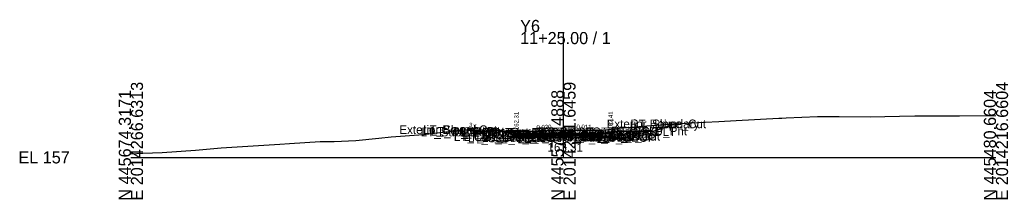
# Model space of a CAD drawing. Extents: x -26 to 203, y -10 to 4529.
# Drawn here: x -25.7 to 202.8, y 2490.3 to 2531.8 of the extents above; entities that cross this region are included whole.
import ezdxf

# ---------------------------------------------------------------- set-up
doc = ezdxf.new("R2010")
doc.units = 0
for name, color, linetype in [('Default', 7, 'Continuous'), ('Exist Cross Section Cell', 7, 'Continuous'), ('Exist XS Center Line Elevation Label', 7, 'Continuous'), ('Exist XS Ground Line', 7, 'Continuous'), ('Prop CMT Conc Surface', 7, 'Continuous'), ('Prop CMT Concrete Structures', 7, 'Continuous'), ('Prop CMT Pvmt Course 1', 7, 'Continuous'), ('Prop CMT Pvmt Course 1 CG', 7, 'Continuous'), ('Prop CMT Pvmt Course 2', 7, 'Continuous'), ('Prop CMT Pvmt Course 3', 7, 'Continuous'), ('Prop CMT Pvmt Surface', 7, 'Continuous'), ('Prop CMT Slope Grass', 7, 'Continuous'), ('Prop CMT Subgrade Earthwork', 7, 'Continuous'), ('Prop XS Earthwork Shape', 7, 'Continuous'), ('Prop XS Hydro Elevations', 7, 'Continuous'), ('Prop XS SE Text', 7, 'Continuous'), ('Prop XS Side Slope Text', 7, 'Continuous'), ('Scratch_Level_0', 7, 'Continuous')]:
    doc.layers.add(name, color=color, linetype=linetype)

msp = doc.modelspace()

# ---------------------------------------------------------------- linework, layer by layer
at = {"layer": 'Exist Cross Section Cell'}
for p, q in [((100, 2500), (100, 2529.01)), ((0, 2500), (100, 2500)), ((100, 2500), (200, 2500))]:
    msp.add_line(p, q, dxfattribs=at)
at = {"layer": 'Exist XS Ground Line'}
msp.add_lwpolyline([(0, 2500.81), (2.74, 2500.95), (7.2, 2501.15), (14.96, 2501.67), (20.87, 2502.17), (34.46, 2503.03), (36.65, 2503.19), (43.79, 2503.64), (46.98, 2503.71), (52, 2503.92), (57.31, 2504.47), (60.21, 2504.76), (67.64, 2505.3), (71.45, 2505.76), (77.97, 2506.45), (78.99, 2506.43), (91.3, 2505.96), (95.44, 2506.13), (100, 2506.31), (100.51, 2506.33), (107.31, 2506.3), (109.12, 2506.28), (110.24, 2506.44), (113.68, 2506.85), (120.24, 2507.39), (129.61, 2507.98), (135.92, 2508.32), (139.94, 2508.52), (149.84, 2509.04), (150.52, 2509.06), (151.51, 2509.11), (158.73, 2509.46), (160.6, 2509.48), (163.76, 2509.49), (170.93, 2509.35), (177.68, 2509.55), (181.25, 2509.58), (191.6, 2509.58), (200, 2509.67)], dxfattribs=at)
at = {"layer": 'Prop CMT Conc Surface'}
for points in [[(89.12, 2505.31), (89.11, 2505.81), (88.61, 2505.81)], [(91.12, 2505.43), (89.12, 2505.31)], [(108.92, 2505.51), (110.92, 2505.41)], [(110.92, 2505.41), (110.92, 2505.91), (111.42, 2505.91)]]:
    msp.add_lwpolyline(points, dxfattribs=at)
at = {"layer": 'Prop CMT Concrete Structures'}
for points in [[(91.12, 2505.43), (89.12, 2505.31), (89.11, 2505.81), (88.61, 2505.81)], [(88.61, 2505.81), (88.62, 2504.8), (91.12, 2504.85)], [(91.12, 2504.85), (91.12, 2505.43)], [(108.92, 2505.51), (110.92, 2505.41), (110.92, 2505.91), (111.42, 2505.91)], [(111.42, 2505.91), (111.42, 2504.9), (108.92, 2504.93)], [(108.92, 2504.93), (108.92, 2505.51)]]:
    msp.add_lwpolyline(points, dxfattribs=at)
at = {"layer": 'Prop CMT Pvmt Course 1'}
for points in [[(100, 2505.61), (91.12, 2505.43)], [(91.12, 2505.43), (91.12, 2505.18)], [(91.12, 2505.18), (100, 2505.36)], [(100, 2505.36), (100, 2505.61)], [(100, 2505.61), (108.92, 2505.51)], [(100, 2505.36), (100, 2505.61)], [(108.92, 2505.26), (100, 2505.36)], [(108.92, 2505.51), (108.92, 2505.26)]]:
    msp.add_lwpolyline(points, dxfattribs=at)
msp.add_lwpolyline([(100, 2505.36), (100, 2505.49), (100, 2505.49), (100, 2505.36)], close=True, dxfattribs=at)
msp.add_lwpolyline([(100, 2505.36), (100, 2505.49), (100, 2505.49), (100, 2505.36)], close=True, dxfattribs=at)
at = {"layer": 'Prop CMT Pvmt Course 1 CG'}
for points in [[(91.12, 2504.85), (88.12, 2504.79), (87.82, 2504.49)], [(91.12, 2504.56), (91.12, 2504.85)], [(108.92, 2504.93), (111.92, 2504.9), (112.21, 2504.6)], [(108.92, 2504.64), (108.92, 2504.93)], [(87.82, 2504.49), (91.12, 2504.56)], [(112.21, 2504.6), (108.92, 2504.64)]]:
    msp.add_lwpolyline(points, dxfattribs=at)
at = {"layer": 'Prop CMT Pvmt Course 2'}
for points in [[(100, 2505.36), (91.12, 2505.18)], [(91.12, 2505.18), (91.12, 2504.93)], [(91.12, 2504.93), (100, 2505.11)], [(100, 2505.11), (100, 2505.36)], [(100, 2505.11), (100, 2505.36)], [(100, 2505.36), (108.92, 2505.26)], [(108.92, 2505.01), (100, 2505.11)], [(108.92, 2505.26), (108.92, 2505.01)]]:
    msp.add_lwpolyline(points, dxfattribs=at)
at = {"layer": 'Prop CMT Pvmt Course 3'}
for points in [[(100, 2505.11), (91.12, 2504.93)], [(91.12, 2504.93), (91.12, 2504.56)], [(91.12, 2504.56), (100, 2504.74)], [(100, 2504.74), (100, 2505.11)], [(100, 2505.11), (108.92, 2505.01)], [(100, 2504.74), (100, 2505.11)], [(108.92, 2504.64), (100, 2504.74)], [(108.92, 2505.01), (108.92, 2504.64)]]:
    msp.add_lwpolyline(points, dxfattribs=at)
at = {"layer": 'Prop CMT Pvmt Surface'}
for points in [[(100, 2505.61), (91.12, 2505.43)], [(100, 2505.61), (108.92, 2505.51)]]:
    msp.add_lwpolyline(points, dxfattribs=at)
at = {"layer": 'Prop CMT Slope Grass'}
for points in [[(111.42, 2505.91), (120.92, 2506.1), (125.84, 2507.74)], [(88.61, 2505.81), (79.11, 2506), (77.83, 2506.43)]]:
    msp.add_lwpolyline(points, dxfattribs=at)
at = {"layer": 'Prop CMT Subgrade Earthwork'}
for points in [[(91.12, 2504.56), (87.82, 2504.49), (86.45, 2505.86)], [(100, 2504.74), (91.12, 2504.56)], [(100, 2504.74), (108.92, 2504.64)], [(108.92, 2504.64), (112.21, 2504.6), (113.57, 2505.95)]]:
    msp.add_lwpolyline(points, dxfattribs=at)
at = {"layer": 'Prop XS Earthwork Shape'}
for points in [[(100.51, 2506.33), (107.31, 2506.3), (109.12, 2506.28), (110.24, 2506.44), (113.68, 2506.85), (120.24, 2507.39), (125.84, 2507.74), (120.92, 2506.1), (113.57, 2505.95), (111.42, 2505.91), (110.92, 2505.91), (110.92, 2505.41), (108.92, 2505.51), (100, 2505.61), (91.12, 2505.43), (89.12, 2505.31), (89.11, 2505.81), (88.61, 2505.81), (86.45, 2505.86), (79.11, 2506), (77.83, 2506.43), (77.97, 2506.45), (78.99, 2506.43), (91.3, 2505.96), (95.44, 2506.13), (100, 2506.31)], [(91.12, 2504.85), (91.12, 2505.43), (100, 2505.61), (108.92, 2505.51), (108.92, 2504.93), (111.42, 2504.9), (111.42, 2505.91), (113.57, 2505.95), (112.21, 2504.6), (108.92, 2504.64), (100, 2504.74), (91.12, 2504.56), (87.82, 2504.49), (86.45, 2505.86), (88.61, 2505.81), (88.62, 2504.8)], [(91.12, 2505.43), (89.12, 2505.31), (89.11, 2505.81), (88.61, 2505.81), (88.62, 2504.8), (91.12, 2504.85)], [(110.92, 2505.41), (110.92, 2505.91), (111.42, 2505.91), (111.42, 2504.9), (108.92, 2504.93), (108.92, 2505.51)]]:
    msp.add_lwpolyline(points, close=True, dxfattribs=at)

# ---------------------------------------------------------------- texts
at = {"layer": 'Default'}
msp.add_text('-', height=0.0001, dxfattribs=at).set_placement((0, 2500))
at = {"layer": 'Exist Cross Section Cell'}
for s, p in [('Y6', (90, 2529.01)), ('11+25.00 / 1', (90, 2526.21)), ('EL 157', (-26, 2498.6))]:
    msp.add_text(s, height=2.8, dxfattribs=at).set_placement(p)
for s, p in [('E 2014266.6313', (2.8, 2490)), ('E 2014241.6459', (102.8, 2490)), ('E 2014216.6604', (202.8, 2490)), ('N 445674.3171', (0, 2490)), ('N 445577.4888', (100, 2490)), ('N 445480.6604', (200, 2490))]:
    msp.add_text(s, height=2.8, rotation=90, dxfattribs=at).set_placement(p)
at = {"layer": 'Exist XS Center Line Elevation Label'}
msp.add_text('163.31', height=2, dxfattribs=at).set_placement((96.32, 2501.31))
at = {"layer": 'Prop XS Hydro Elevations'}
for s, p in [('162.31', (89.62, 2506.31)), ('162.41', (111.42, 2506.41))]:
    msp.add_text(s, height=1, rotation=90, dxfattribs=at).set_placement(p)
at = {"layer": 'Prop XS SE Text'}
for s, rotation, p in [('0.020', 1.1458, (93.79, 2506.49)), ('0.011', 359.3598, (103.02, 2506.58))]:
    msp.add_text(s, height=1, rotation=rotation, dxfattribs=at).set_placement(p)
at = {"layer": 'Prop XS Side Slope Text'}
for rotation, p in [(341.5652, (78.01, 2507.16)), (18.4332, (122.4, 2507.38))]:
    msp.add_text('3:1', height=1, rotation=rotation, dxfattribs=at).set_placement(p)
at = {"layer": 'Scratch_Level_0'}
for s, p in [('Exterior Boundary', (62.08, 2505.4)), ('LT_Slope_Cut', (67.57, 2505.4)), ('LT_CSLP_Pnt', (69.29, 2505)), ('RT_Sub_Trench_Out_DLT', (94.09, 2504.95)), ('Exterior Boundary', (110, 2506.75)), ('RT_CSLP_Pnt', (111.04, 2505.1)), ('RT_Slope_Cut', (115.45, 2506.75)), ('LT_Sub_Trench_Out_DLT', (67.02, 2504.86)), ('LT_CG1_Shelf_Out', (74.67, 2503.79)), ('LT_CG_Top_Face', (76.37, 2504.81)), ('LT_CG_Top_BOC', (76.9, 2504.81)), ('LT_CG_Bot_BOC', (76.93, 2503.8)), ('LT_CG_Top_Gut', (77.35, 2504.31)), ('LT_Sub_OEOP', (77.93, 2503.49)), ('LT_CG_Bot_IE', (81.03, 2503.85)), ('LT_Sub_OEOT', (81.19, 2503.56)), ('LT_PV2_OEOT', (81.29, 2504.18)), ('LT_PV3_OEOT', (81.29, 2503.93)), ('LT_PV1_OEOT', (81.86, 2504.43)), ('RT_Sub_OEEOP', (89.17, 2503.74)), ('LT_Sub_OEEOP', (89.21, 2503.74)), ('RT_PV2_OEEOP', (89.26, 2504.36)), ('RT_PV3_OEEOP', (89.26, 2504.11)), ('LT_PV2_OEEOP', (89.31, 2504.36)), ('LT_PV3_OEEOP', (89.31, 2504.11)), ('RT_PV1_OEEOP', (89.83, 2504.49)), ('LT_PV1_OEEOP', (89.87, 2504.49)), ('RT_PV2_IEEOP', (89.91, 2504.36)), ('LT_PV2_IEEOP', (89.95, 2504.36)), ('RT_PV1_IEEOP', (90.47, 2504.49)), ('LT_PV1_IEEOP', (90.52, 2504.49)), ('PV2_PGL', (93.91, 2504.36)), ('PV1_PGL', (94.47, 2504.61)), ('RT_CG_Top_Face', (98.13, 2504.91)), ('RT_CG1_Shelf_Out', (98.42, 2503.9)), ('RT_CG_Bot_IE', (98.78, 2503.93)), ('RT_Sub_OEOT', (98.95, 2503.64)), ('RT_PV2_OEOT', (99.04, 2504.26)), ('RT_PV3_OEOT', (99.04, 2504.01)), ('RT_CG_Top_Gut', (99.11, 2504.41)), ('RT_PV1_OEOT', (99.61, 2504.51)), ('RT_CG_Top_BOC', (99.66, 2504.91)), ('RT_CG_Bot_BOC', (99.69, 2503.9)), ('RT_Sub_OEOP', (102.28, 2503.6))]:
    msp.add_text(s, height=2, dxfattribs=at).set_placement(p)

doc.saveas('drawing.dxf')
